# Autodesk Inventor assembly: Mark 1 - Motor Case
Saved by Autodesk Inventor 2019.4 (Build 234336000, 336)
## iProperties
Created: 2020-06
Part Number: Mark 1 - Motor Case
Document SubType Name: Assembly
Designer: Administrator
Title: Mark 1 - Motor Case v8
Author: Administrator
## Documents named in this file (2)
- c:\worker\convert-fusion-r04\tmp\job-1\1344\output\files\114f427a-bc40-494f-9b3d-9b9b42ba4950\01d411da-5385-4c35-8f43-e0f21a09c320.iam
- c:\worker\convert-fusion-r04\tmp\job-1\1344\output\files\114f427a-bc40-494f-9b3d-9b9b42ba4950\Mark 1 - Motor Case v8.ipt
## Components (1 placed, 1 different names)
1. Mark 1 - Motor Case v8
